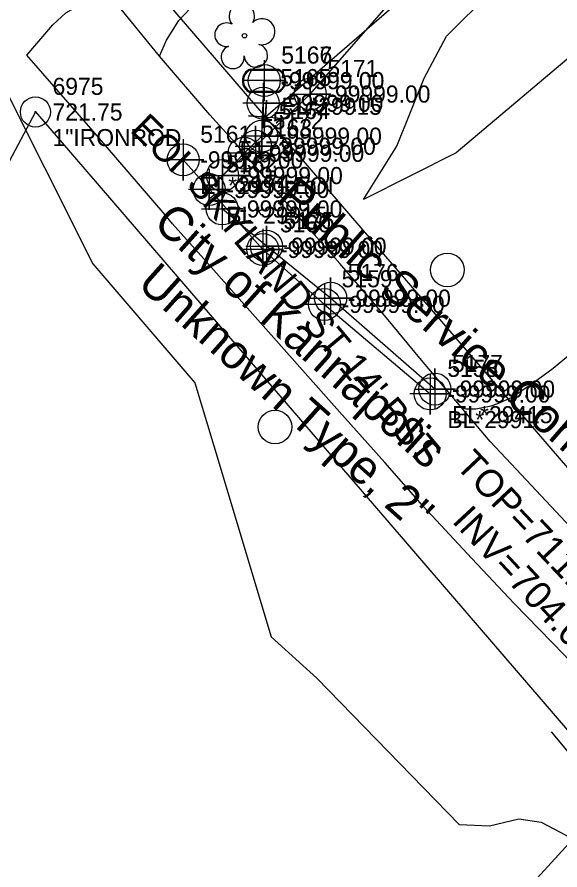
# Model space of a CAD drawing. Extents: x 1516784 to 1522736, y 634838 to 639369.
# Drawn here: x 1521003.1 to 1521082.4, y 637722.6 to 637847.3 of the extents above; entities that cross this region are included whole.
import ezdxf

# ---------------------------------------------------------------- set-up
doc = ezdxf.new("R2010")
doc.units = 0
for name, color, linetype in [('COGO Default Point Number', 7, 'Continuous'), ('Exist Hydro Jurisdictional Stream or Body of Water Mitigable', 7, 'Continuous'), ('Exist Other Culture Fence Line', 7, 'Continuous'), ('Exist Property Corner CELL', 7, 'Continuous'), ('Exist Property Iron Pin CELL', 7, 'Continuous'), ('Exist Property Iron Pin Cogo Comment', 7, 'Continuous'), ('Exist Property Iron Pin Cogo Elevation', 7, 'Continuous'), ('Exist Property Iron Pin Cogo Number', 7, 'Continuous'), ('Exist Property Line', 7, 'Continuous'), ('Exist Right of Way Line', 7, 'Continuous'), ('Exist Roads EOP Text', 7, 'Continuous'), ('Exist Structure Minor Drop Inlet Top Elevation', 7, 'Continuous'), ('Exist Structure Minor Pipes RCP 24 Inch', 7, 'Continuous'), ('Exist Structure Minor Pipes RCP 24 Inch Invert', 7, 'Continuous'), ('Exist Utilities Gas UG Line SUE LOS B', 7, 'Continuous'), ('Exist Utilities Gas UG Line SUE LOS B Cogo Comment', 7, 'Continuous'), ('Exist Utilities Gas UG Line SUE LOS B Cogo Elevation', 7, 'Continuous'), ('Exist Utilities Gas UG Line SUE LOS B Cogo Number', 7, 'Continuous'), ('Exist Utilities Gas UG Line SUE LOS B Cogo Point CELL', 7, 'Continuous'), ('Exist Utilities Gas UG Line SUE LOS B Text', 7, 'Continuous'), ('Exist Utilities Other Pole CELL', 7, 'Continuous'), ('Exist Utilities Water Meter CELL', 7, 'Continuous'), ('Exist Utilities Water Meter Cogo Elevation', 7, 'Continuous'), ('Exist Utilities Water Meter Cogo Number', 7, 'Continuous'), ('Exist Utilities Water Meter Text', 7, 'Continuous'), ('Exist Utilities Water UG Line SUE LOS B', 7, 'Continuous'), ('Exist Utilities Water UG Line SUE LOS B Cogo Comment', 7, 'Continuous'), ('Exist Utilities Water UG Line SUE LOS B Cogo Elevation', 7, 'Continuous'), ('Exist Utilities Water UG Line SUE LOS B Cogo Number', 7, 'Continuous'), ('Exist Utilities Water UG Line SUE LOS B Cogo Point CELL', 7, 'Continuous'), ('Exist Utilities Water UG Line SUE LOS B Text', 7, 'Continuous'), ('Exist Vegetation Tree CELL', 7, 'Continuous'), ('Exist Vegetation Woods Line', 7, 'Continuous'), ('Scratch_Level_5', 7, 'Continuous')]:
    doc.layers.add(name, color=color, linetype=linetype)

msp = doc.modelspace()

# ---------------------------------------------------------------- linework, layer by layer
at = {"layer": 'COGO Default Point Number'}
for points in [[(1521024.71, 637818.38), (1521014.21, 637830.63), (1521004.48, 637841.77), (1521008.29, 637846.16), (1521010.17, 637847.92), (1521012.45, 637849.19), (1521016.76, 637850.39)], [(1521083.92, 637772.74), (1521076.74, 637780.35), (1521072.18, 637785.23), (1521067.94, 637790.25), (1521061.93, 637797.42), (1521057.02, 637803.31), (1521050.2, 637811.26), (1521045.42, 637816.72), (1521042.31, 637820.3), (1521038.76, 637824.42), (1521034.94, 637828.95), (1521031.23, 637833.02), (1521023.86, 637841.59), (1521016.76, 637850.39)], [(1521069.51, 637768.15), (1521062.34, 637775.86), (1521056.78, 637782.16), (1521050.18, 637789.6), (1521044.76, 637795.68), (1521040.21, 637800.83), (1521035.89, 637805.66), (1521030.37, 637811.97), (1521025.8, 637817.06), (1521024.71, 637818.38)], [(1521087.64, 637749.05), (1521082.98, 637754.05), (1521075.69, 637761.56), (1521069.51, 637768.15)]]:
    msp.add_lwpolyline(points, dxfattribs=at)
at = {"layer": 'Exist Hydro Jurisdictional Stream or Body of Water Mitigable'}
for points in [[(1521023.86, 637841.59), (1521024.89, 637843.93), (1521026.68, 637846.81), (1521030, 637850.37), (1521035.31, 637856.48), (1521043.88, 637865.79)], [(1521067.94, 637790.25), (1521068.63, 637790.04), (1521070.07, 637790.01), (1521072.34, 637790.46), (1521073.29, 637790.79), (1521075.29, 637791.67), (1521078.47, 637793.81), (1521081.39, 637795.96), (1521083.99, 637798.12), (1521086.91, 637800.31), (1521095.02, 637807.54)]]:
    msp.add_lwpolyline(points, dxfattribs=at)
at = {"layer": 'Exist Other Culture Fence Line'}
msp.add_lwpolyline([(1521225.87, 637572.22), (1521205.33, 637596.42), (1521189.76, 637614.63), (1521169.15, 637639), (1521152.7, 637658.2), (1521133.11, 637681.5), (1521116.78, 637700.6), (1521104.24, 637715.16), (1521081.14, 637742.8)], dxfattribs=at)
at = {"layer": 'Exist Property Corner CELL'}
msp.add_line((1521039.35, 637832.7), (1521039.35, 637832.7), dxfattribs=at)
msp.add_lwpolyline([(1521039.17, 637830.21), (1521039.53, 637835.19), (1521039.35, 637832.7), (1521036.86, 637832.88), (1521041.84, 637832.52)], dxfattribs=at)
at = {"layer": 'Exist Property Iron Pin CELL'}
for radius in [2.2, 0.0707]:
    msp.add_circle((1521005.75, 637833.44), radius, dxfattribs=at)
at = {"layer": 'Exist Property Line'}
for p, q in [((1521157.11, 637934.57), (1521039.35, 637832.7)), ((1521005.75, 637833.44), (1520930.04, 637691.4))]:
    msp.add_line(p, q, dxfattribs=at)
at = {"layer": 'Exist Right of Way Line'}
for p, q in [((1521018.53, 637856.92), (1521252.87, 637584.32)), ((1521005.75, 637833.44), (1521233.91, 637568.02))]:
    msp.add_line(p, q, dxfattribs=at)
at = {"layer": 'Exist Structure Minor Pipes RCP 24 Inch'}
msp.add_line((1520892.8, 637516.96), (1521109.32, 637754.63), dxfattribs=at)
at = {"layer": 'Exist Utilities Gas UG Line SUE LOS B'}
for points in [[(1521033.03, 637819.26), (1521033.1, 637824.14), (1521037.92, 637828.43), (1521045.9, 637836.06), (1521059.05, 637851.17), (1521058.77, 637853.29)], [(1521064.11, 637792.92), (1521048.88, 637806.22), (1521039.49, 637813.81), (1521033.03, 637819.26)]]:
    msp.add_lwpolyline(points, dxfattribs=at)
at = {"layer": 'Exist Utilities Gas UG Line SUE LOS B Cogo Point CELL'}
for points in [[(1521042.9, 637836.06), (1521048.9, 637836.06), (1521045.9, 637836.06), (1521045.9, 637839.06), (1521045.9, 637833.06)], [(1521034.92, 637828.43), (1521040.92, 637828.43), (1521037.92, 637828.43), (1521037.92, 637831.43), (1521037.92, 637825.43)], [(1521030.1, 637824.14), (1521036.1, 637824.14), (1521033.1, 637824.14), (1521033.1, 637827.14), (1521033.1, 637821.14)], [(1521030.03, 637819.26), (1521036.03, 637819.26), (1521033.03, 637819.26), (1521033.03, 637822.26), (1521033.03, 637816.26)], [(1521036.49, 637813.81), (1521042.49, 637813.81), (1521039.49, 637813.81), (1521039.49, 637816.81), (1521039.49, 637810.81)], [(1521045.88, 637806.22), (1521051.88, 637806.22), (1521048.88, 637806.22), (1521048.88, 637809.22), (1521048.88, 637803.22)], [(1521061.11, 637792.92), (1521067.11, 637792.92), (1521064.11, 637792.92), (1521064.11, 637795.92), (1521064.11, 637789.92)]]:
    msp.add_lwpolyline(points, dxfattribs=at)
for centre in [(1521045.9, 637836.06), (1521037.92, 637828.43), (1521033.1, 637824.14), (1521033.03, 637819.26), (1521039.49, 637813.81), (1521048.88, 637806.22), (1521064.11, 637792.92)]:
    msp.add_circle(centre, 2.34, dxfattribs=at)
at = {"layer": 'Exist Utilities Other Pole CELL'}
for centre in [(1521065.93, 637810.35), (1521040.75, 637787.37)]:
    msp.add_circle(centre, 2.46, dxfattribs=at)
at = {"layer": 'Exist Utilities Water Meter CELL'}
msp.add_line((1521039.16, 637838.01), (1521039.16, 637838.01), dxfattribs=at)
for points in [[(1521037.12, 637839.71), (1521041.19, 637839.71)], [(1521037.12, 637839.57), (1521041.19, 637839.57)], [(1521041.19, 637836.45), (1521037.09, 637836.45)], [(1521041.19, 637836.31), (1521037.09, 637836.31)]]:
    msp.add_lwpolyline(points, dxfattribs=at)
for centre, radius, start, end in [((1521037.85, 637838), 1.86, 113.178, 245.9794), ((1521037.86, 637838), 1.73, 115.3009, 243.7824), ((1521040.45, 637838.01), 1.86, 293.6483, 66.3084), ((1521040.46, 637838.01), 1.73, 295.1272, 64.8728)]:
    msp.add_arc(centre, radius, start, end, dxfattribs=at)
at = {"layer": 'Exist Utilities Water UG Line SUE LOS B'}
for points in [[(1521031.13, 637822.11), (1521036.23, 637827.4), (1521038.81, 637829.9), (1521039.03, 637834.72), (1521039.18, 637838.03)], [(1521027.33, 637826.44), (1521038.97, 637813.34), (1521047.99, 637805.3), (1521063.43, 637792.2)]]:
    msp.add_lwpolyline(points, dxfattribs=at)
at = {"layer": 'Exist Utilities Water UG Line SUE LOS B Cogo Point CELL'}
for points in [[(1521039.18, 637841.03), (1521039.18, 637835.03), (1521039.18, 637838.03), (1521042.18, 637838.03), (1521036.18, 637838.03)], [(1521039.03, 637837.72), (1521039.03, 637831.72), (1521039.03, 637834.72), (1521042.03, 637834.72), (1521036.03, 637834.72)], [(1521038.81, 637832.9), (1521038.81, 637826.9), (1521038.81, 637829.9), (1521041.81, 637829.9), (1521035.81, 637829.9)], [(1521036.23, 637830.4), (1521036.23, 637824.4), (1521036.23, 637827.4), (1521039.23, 637827.4), (1521033.23, 637827.4)], [(1521027.33, 637829.44), (1521027.33, 637823.44), (1521027.33, 637826.44), (1521030.33, 637826.44), (1521024.33, 637826.44)], [(1521031.13, 637825.11), (1521031.13, 637819.11), (1521031.13, 637822.11), (1521034.13, 637822.11), (1521028.13, 637822.11)], [(1521038.97, 637816.34), (1521038.97, 637810.34), (1521038.97, 637813.34), (1521041.97, 637813.34), (1521035.97, 637813.34)], [(1521047.99, 637808.3), (1521047.99, 637802.3), (1521047.99, 637805.3), (1521050.99, 637805.3), (1521044.99, 637805.3)], [(1521063.43, 637795.2), (1521063.43, 637789.2), (1521063.43, 637792.2), (1521066.43, 637792.2), (1521060.43, 637792.2)]]:
    msp.add_lwpolyline(points, dxfattribs=at)
for centre in [(1521039.18, 637838.03), (1521039.03, 637834.72), (1521038.81, 637829.9), (1521027.33, 637826.44), (1521036.23, 637827.4), (1521031.13, 637822.11), (1521038.97, 637813.34), (1521047.99, 637805.3), (1521063.43, 637792.2)]:
    msp.add_circle(centre, 2.34, dxfattribs=at)
at = {"layer": 'Exist Vegetation Tree CELL'}
msp.add_line((1521036.29, 637844.59), (1521036.29, 637844.59), dxfattribs=at)
msp.add_circle((1521036.29, 637844.59), 0.326, dxfattribs=at)
for centre, radius, start, end in [((1521035.9, 637847.46), 1.86, 330.1651, 219.7134), ((1521033.68, 637844.74), 1.73, 62.6636, 279.3457), ((1521038.84, 637845.18), 1.9, 257.1011, 134.1999), ((1521034.58, 637841.47), 1.69, 111.5671, 6.231), ((1521037.96, 637841.69), 1.7, 181.2822, 74.56)]:
    msp.add_arc(centre, radius, start, end, dxfattribs=at)
at = {"layer": 'Exist Vegetation Woods Line'}
for points in [[(1521110.76, 637864.29), (1521067.24, 637827.48), (1521053.7, 637820.64), (1521058.54, 637828.43), (1521062.56, 637838.37), (1521065.83, 637844.51), (1521072.27, 637851)], [(1520999.96, 637839.4), (1521014.13, 637811.25), (1521029.02, 637793.85), (1521031.8, 637784.59), (1521040.19, 637756.66), (1521046.85, 637750.63), (1521067.67, 637729.24), (1521072.08, 637729.04), (1521076.36, 637730.08), (1521079.64, 637729.57), (1521083.36, 637727.64), (1521087.34, 637723.32), (1521093.17, 637715.95)]]:
    msp.add_lwpolyline(points, dxfattribs=at)

# ---------------------------------------------------------------- texts
at = {"layer": 'Exist Property Iron Pin Cogo Comment'}
msp.add_text('1"IRONROD', height=2.5, dxfattribs=at).set_placement((1521008.25, 637828.44))
at = {"layer": 'Exist Property Iron Pin Cogo Elevation'}
msp.add_text('721.75', height=2.5, dxfattribs=at).set_placement((1521008.25, 637832.19))
at = {"layer": 'Exist Property Iron Pin Cogo Number'}
msp.add_text('6975', height=2.5, dxfattribs=at).set_placement((1521008.25, 637835.94))
at = {"layer": 'Exist Roads EOP Text'}
msp.add_text("SKYLAND ST 14' BST", height=4, rotation=309.827, dxfattribs=at).set_placement((1521027.67, 637822.82))
at = {"layer": 'Exist Structure Minor Drop Inlet Top Elevation'}
msp.add_text("TOP=711.07'", height=4, rotation=313.3537, dxfattribs=at).set_placement((1521066.97, 637781.65))
at = {"layer": 'Exist Structure Minor Pipes RCP 24 Inch Invert'}
msp.add_text("INV=704.04'", height=4, rotation=312.8848, dxfattribs=at).set_placement((1521066.48, 637773.52))
at = {"layer": 'Exist Utilities Gas UG Line SUE LOS B Cogo Comment'}
msp.add_text('EL*29415', height=2.5, dxfattribs=at).set_placement((1521066.61, 637787.92))
at = {"layer": 'Exist Utilities Gas UG Line SUE LOS B Cogo Elevation'}
for p in [(1521048.4, 637834.81), (1521040.42, 637827.18), (1521035.6, 637822.89), (1521035.53, 637818.01), (1521041.99, 637812.56), (1521051.38, 637804.97), (1521066.61, 637791.67)]:
    msp.add_text('-99999.00', height=2.5, dxfattribs=at).set_placement(p)
at = {"layer": 'Exist Utilities Gas UG Line SUE LOS B Cogo Number'}
for s, p in [('5171', (1521048.4, 637838.56)), ('5172', (1521040.42, 637830.93)), ('5173', (1521035.6, 637826.64)), ('5174', (1521035.53, 637821.76)), ('5175', (1521041.99, 637816.31)), ('5176', (1521051.38, 637808.72)), ('5177', (1521066.61, 637795.42))]:
    msp.add_text(s, height=2.5, dxfattribs=at).set_placement(p)
at = {"layer": 'Exist Utilities Gas UG Line SUE LOS B Text'}
msp.add_text('Public Service Company Of N C Inc., 2 ", Steel', height=5, rotation=318.8829, dxfattribs=at).set_placement((1521040.72, 637820.48))
at = {"layer": 'Exist Utilities Water Meter Cogo Elevation'}
msp.add_text('-99999.00', height=2.5, dxfattribs=at).set_placement((1521041.66, 637836.76))
at = {"layer": 'Exist Utilities Water Meter Cogo Number'}
msp.add_text('5167', height=2.5, dxfattribs=at).set_placement((1521041.66, 637840.51))
at = {"layer": 'Exist Utilities Water Meter Text'}
msp.add_text('EOI', height=4, rotation=315.5627, dxfattribs=at).set_placement((1521019.44, 637830.67))
at = {"layer": 'Exist Utilities Water UG Line SUE LOS B Cogo Comment'}
for s, p in [('EL*29915', (1521041.68, 637833.03)), ('EL*2991 EOI', (1521029.83, 637821.44)), ('BL*29915', (1521033.63, 637817.11)), ('BL*2991', (1521065.93, 637787.2))]:
    msp.add_text(s, height=2.5, dxfattribs=at).set_placement(p)
at = {"layer": 'Exist Utilities Water UG Line SUE LOS B Cogo Elevation'}
for p in [(1521041.68, 637836.78), (1521041.53, 637833.47), (1521041.31, 637828.65), (1521029.83, 637825.19), (1521038.73, 637826.15), (1521033.63, 637820.86), (1521041.47, 637812.09), (1521050.49, 637804.05), (1521065.93, 637790.95)]:
    msp.add_text('-99999.00', height=2.5, dxfattribs=at).set_placement(p)
at = {"layer": 'Exist Utilities Water UG Line SUE LOS B Cogo Number'}
for s, p in [('5166', (1521041.68, 637840.53)), ('5165', (1521041.53, 637837.22)), ('5164', (1521041.31, 637832.4)), ('5161', (1521029.83, 637828.94)), ('5163', (1521038.73, 637829.9)), ('5162', (1521033.63, 637824.61)), ('5160', (1521041.47, 637815.84)), ('5159', (1521050.49, 637807.8)), ('5158', (1521065.93, 637794.7))]:
    msp.add_text(s, height=2.5, dxfattribs=at).set_placement(p)
at = {"layer": 'Exist Utilities Water UG Line SUE LOS B Text'}
for s, p in [('City of Kannapolis', (1521022.75, 637816.85)), ('Unknown Type, 2"', (1521020.45, 637808.02))]:
    msp.add_text(s, height=5, rotation=318.2886, dxfattribs=at).set_placement(p)
at = {"layer": 'Scratch_Level_5'}
msp.add_text('COLUMN LOCATION', height=500, rotation=335.0373, dxfattribs=at).set_placement((1516680.97, 637558.94))

doc.saveas('drawing.dxf')
